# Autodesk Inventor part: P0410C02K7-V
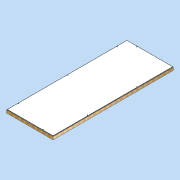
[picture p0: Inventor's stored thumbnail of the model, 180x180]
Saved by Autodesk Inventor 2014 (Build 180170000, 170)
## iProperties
Created: 2011-04
Part Number: P0410C02K7-V
Document SubType Name: Modeling
Designer: david.appleford
Density: 0.197293 g/cm^3
Description: 1w x 2.5w 02 Ceiling Panel - 7 Locks
Mass: 56000 g
Surface Area: 75442.8 cm^2
Volume: 283842 cm^3
Cost Center: £167.00
Material: Generic
Appearance: Wood (Pine)
Justset: False
Title: 1w x 2.5w 02 Ceiling Panel - 7 Locks
Author: david.appleford
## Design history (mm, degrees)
sketch "Sketch1"
  geometry: L1 (0, 0)-(1220, 0); L2 (1220, 0)-(1220, 3050); L3 (1220, 3050)-(0, 3050); L4 (0, 3050)-(0, 0); L5 (34, 3016)-(1186, 3016); L6 (1186, 3016)-(1186, 34); L7 (1186, 34)-(34, 34); L8 (34, 34)-(34, 3016)
  constraints: 16 end point, 4 parallel, 2 perpendicular, 1 horizontal, 3 other
  dimensions: "d0" = 1220 distance between parallel lines of L2 L4 (= w); "d1" = 3050 distance between parallel lines of L1 L3 (= 2.5 x w); "d2" = 34 distance between parallel lines of L5 L3 (= 0.5 x t)
extrude "Extrusion1" new body sketch "Sketch1" distance "d3" = 68 (= t); taper "d4" = 0 deg
sketch "Sketch2"
  geometry: L1 (1186, 3016)-(1186, 34) reference; L2 (34, 3016)-(1186, 3016) reference; L3 (34, 34)-(34, 3016) reference; L4 (1186, 34)-(34, 34) reference; L5 (1176, 3006)-(1176, 44); L6 (1176, 44)-(44, 44); L7 (44, 44)-(44, 3006); L8 (44, 3006)-(1176, 3006); 1 further point
  constraints: 8 end point, 3 other
  dimensions: "d5" = 10 distance between parallel lines of L8 L2
extrude "Extrusion2" join sketch "Sketch2" distance "d6" = 9; taper "d7" = 0 deg
sketch "Sketch3"
  geometry: L1 (-44, 3006)-(-1176, 3006) reference; L2 (-1176, 3006)-(-1176, 44) reference; L3 (-44, 44)-(-44, 3006) reference; L4 (-1176, 44)-(-44, 44) reference; 1 further point
extrude "Extrusion3" join sketch "Sketch3" distance "d8" = 6 (= sw); taper "d9" = 0 deg
sketch "Sketch4"
  geometry: L1 (34, 3016)-(1186, 3016) reference; L2 (1186, 3016)-(1186, 34) reference; L3 (1186, 34)-(34, 34) reference; L4 (34, 34)-(34, 3016) reference; 8 further points
  constraints: 3 vertical alignment
  dimensions: "d10" = 28 distance from line of point (305, 2988) L1 (= k); "d12" = 28 distance from line of L3 point (915, 62) (= k); "d13" = 28 distance from line of point (62, 305) L4 (= k); "d14" = 305 horizontal distance of point (305, 2988) point (0, 0) (= 0.25 x w); "d15" = 610 horizontal distance of point (915, 62) point (305, 2988) (= 0.5 x w); "d16" = 305 vertical distance of point (62, 305) point (0, 0) (= 0.25 x w); "d17" = 1220 distance of point (62, 305) point (62, 1525) (= w); "d18" = 1220 distance of point (62, 2745) point (62, 1525) (= w); "d19" = 610 vertical distance of point (1158, 915) point (62, 305) (= 0.5 x w); "d20" = 1220 distance of point (1158, 915) point (1158, 2135) (= w)
hole "Hole1" sketch "Sketch4" at (305, 2988), (62, 2745), (62, 1525), (62, 305), (1158, 2135), (1158, 915), (915, 62) diameter "d22" = 16.3; stored, may be unused: countersink angle "d26" = 90 deg, drill point angle "d28" = 118 deg; dims "d23" = 6, "d24" = 4, "d25" = 2, "d27" = 8
chamfer "Chamfer1" distance "d29" = 3; stored, may be unused: second distance "d30" = 2, angle "d31" = 45 deg
body "Solid1"
node "Projected Loop1"
other parameters: "w" = 1220 [user parameter; used in 9 equation terms], "t" = 68 [user parameter; used in 2 equation terms], "e" = 16 [user parameter], "sw" = 6 [user parameter; used in 1 equation term], "sc" = 9 [user parameter], "sf" = 12 [user parameter], "k" = 28 [user parameter; used in 3 equation terms], "hd" = 12 [user parameter]
